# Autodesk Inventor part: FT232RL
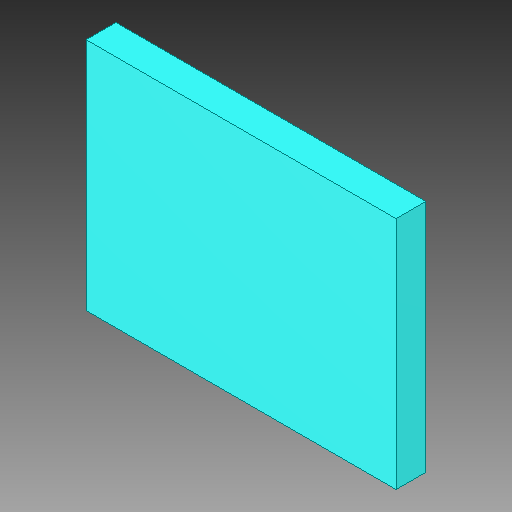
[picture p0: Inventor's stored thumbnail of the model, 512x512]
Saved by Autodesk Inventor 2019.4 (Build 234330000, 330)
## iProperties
Created: 2019-11
Part Number: FT232RL
Material: Generic
Document SubType Name: Modeling
Designer: Willist
Density: 1 g/cm^3
Appearance: SSOP28, FT232RL
Author: Willist
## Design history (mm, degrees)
sketch "SSOP28, FT232RL_37"
  geometry: L1 (-5.202, 3.937)-(5.202, 3.937); L2 (5.202, 3.937)-(5.202, -3.937); L3 (5.202, -3.937)-(-5.202, -3.937); L4 (-5.202, -3.937)-(-5.202, 3.937)
  constraints: 8 end point
extrude "Extrusion1" join sketch "SSOP28, FT232RL_37" distance "d0" = 1; taper "d1" = 0 deg
body "Solid1"
